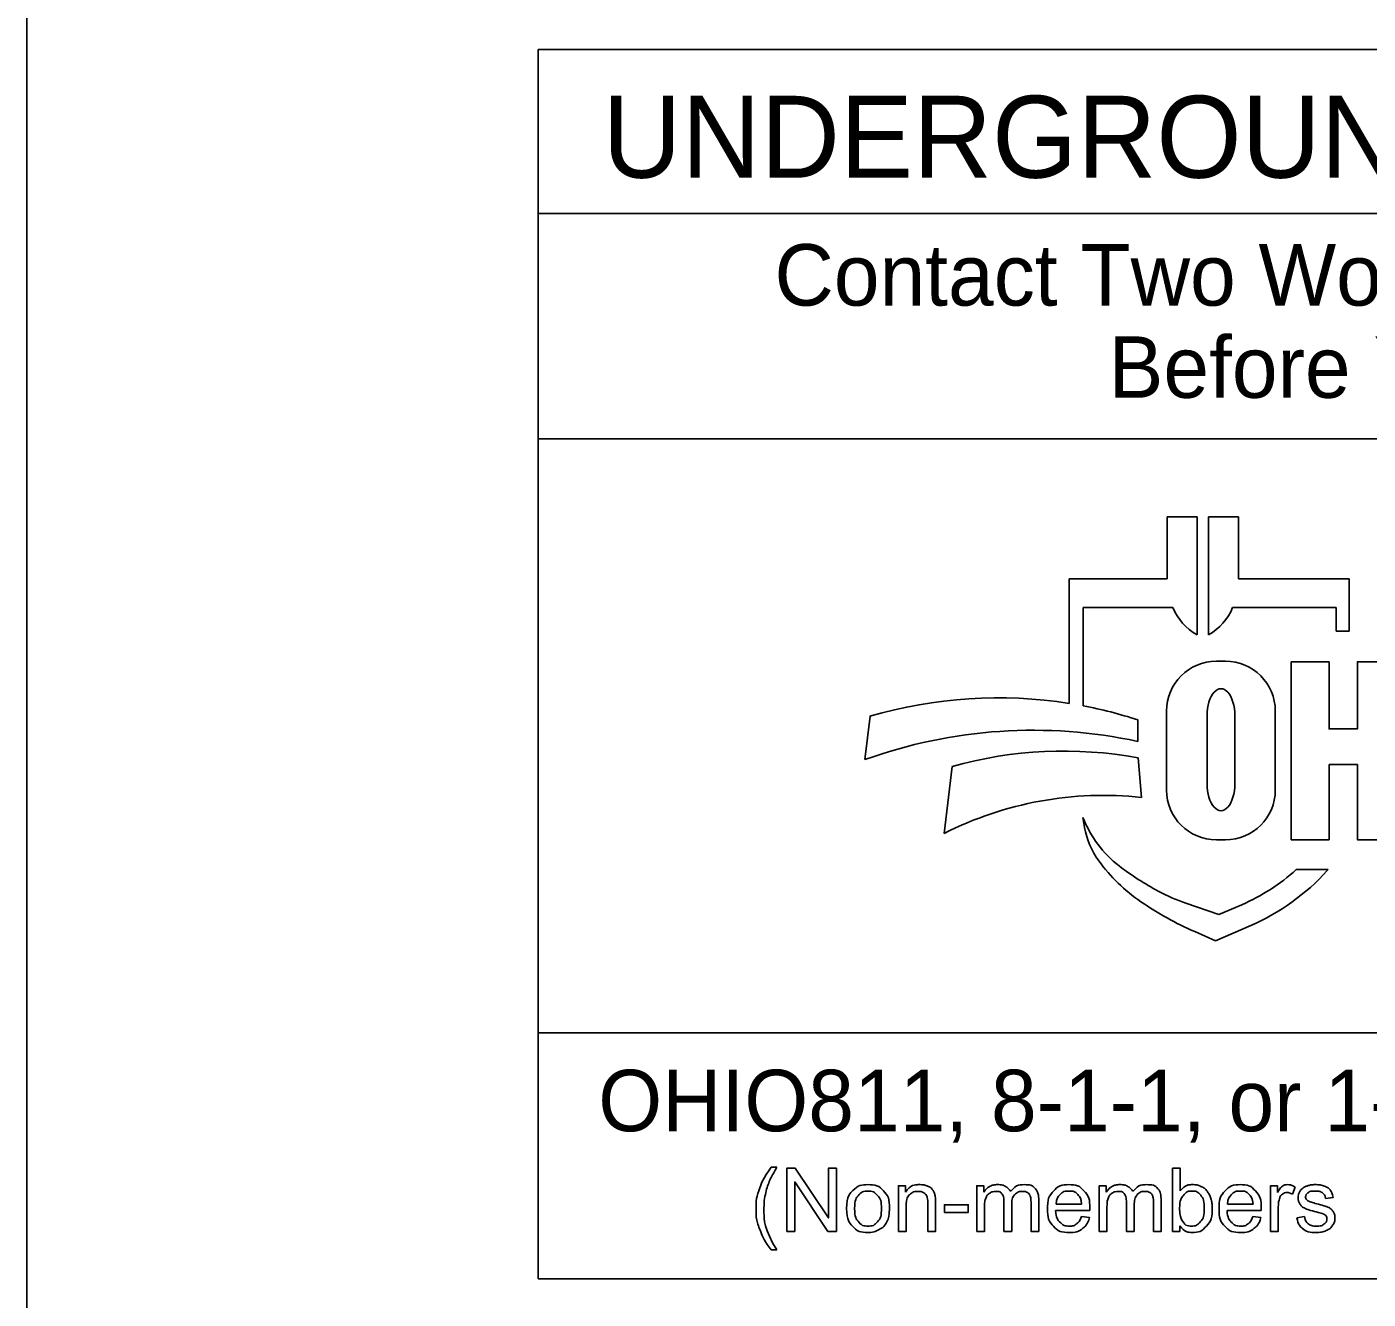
# Model space of a CAD drawing. Extents: x -19.5 to 44.1, y 0 to 22.
# Drawn here: x 2 to 5.062, y 1.775 to 4.678 of the extents above; entities that cross this region are included whole.
import ezdxf

# ---------------------------------------------------------------- set-up
doc = ezdxf.new("R2010")
doc.units = 0
doc.layers.add('SH_Border', color=7, linetype='Continuous')
doc.layers.add('SH_Data', color=7, linetype='Continuous')

msp = doc.modelspace()

# ---------------------------------------------------------------- linework, layer by layer
at = {"layer": 'SH_Border'}
msp.add_lwpolyline([(2, 21.5), (33.5, 21.5), (33.5, 0.5), (2, 0.5)], close=True, dxfattribs=at)
at = {"layer": 'SH_Data'}
for p, q in [((3.1673, 4.6264), (7.6086, 4.6264)), ((3.1673, 1.8214), (3.1673, 4.6264)), ((3.1673, 4.2524), (7.6086, 4.2524)), ((3.1673, 3.7382), (7.6086, 3.7382)), ((4.671, 3.5601), (4.6029, 3.5601)), ((4.6029, 3.5601), (4.6029, 3.4185)), ((4.671, 3.2908), (4.671, 3.5601)), ((4.7655, 3.5601), (4.6974, 3.5601)), ((4.6974, 3.5601), (4.6974, 3.2908)), ((4.7655, 3.4185), (4.7655, 3.5601)), ((4.6029, 3.4185), (4.3794, 3.4185)), ((4.3794, 3.4185), (4.3794, 3.1343)), ((5.0185, 3.4185), (4.7655, 3.4185)), ((5.0185, 3.2994), (5.0185, 3.4185)), ((4.4115, 3.1287), (4.4115, 3.3532)), ((4.4115, 3.3532), (4.6161, 3.3532)), ((4.7523, 3.3532), (4.9889, 3.3532)), ((4.9889, 3.3532), (4.9889, 3.2994)), ((4.9889, 3.2994), (5.0185, 3.2994)), ((4.7361, 3.2305), (4.7152, 3.2305)), ((4.9724, 3.2293), (4.8861, 3.2293)), ((4.8861, 3.2293), (4.8861, 2.823)), ((3.9246, 3.1052), (3.9127, 3.006)), ((4.5357, 3.0476), (4.5357, 3.0969)), ((4.6015, 3.1169), (4.6015, 2.9366)), ((4.6941, 2.951), (4.6941, 3.1064)), ((4.7573, 3.1064), (4.7573, 2.951)), ((4.8497, 2.9366), (4.8497, 3.1169)), ((4.5443, 2.9197), (4.5364, 3.0098)), ((4.1121, 2.9902), (4.0935, 2.8377)), ((4.9724, 2.823), (4.9724, 2.9947)), ((4.4106, 2.8741), (4.4145, 2.8513)), ((4.7152, 2.823), (4.7361, 2.823)), ((4.8861, 2.823), (4.9724, 2.823)), ((4.9703, 2.755), (4.8974, 2.755)), ((4.9683, 2.7527), (4.9703, 2.755)), ((4.7209, 2.6523), (4.6454, 2.6783)), ((4.773, 2.6749), (4.7209, 2.6523)), ((4.6658, 2.6135), (4.7132, 2.5926)), ((4.7132, 2.5926), (4.7936, 2.6275)), ((7.6086, 2.3825), (3.1673, 2.3825)), ((7.6086, 1.8214), (3.1673, 1.8214))]:
    msp.add_line(p, q, dxfattribs=at)
for points in [[(4.9724, 2.9947), (5.0371, 2.9947), (5.0371, 2.823), (5.1234, 2.823), (5.1234, 3.2293), (5.0371, 3.2293), (5.0371, 3.076), (4.9724, 3.076), (4.9724, 3.2293)], [(3.6993, 2.0757), (3.7119, 2.0757)], [(3.7345, 1.9293), (3.7345, 2.0733), (3.754, 2.0733), (3.8298, 1.9602), (3.8298, 2.0733), (3.848, 2.0733), (3.848, 1.9293), (3.8285, 1.9293), (3.7527, 2.0424), (3.7527, 1.9293), (3.7345, 1.9293)], [(4.6316, 1.9293), (4.6153, 1.9293), (4.6153, 2.0733), (4.6329, 2.0733), (4.6329, 2.022)], [(3.9896, 1.9293), (3.9896, 2.0337), (4.0055, 2.0337), (4.0055, 2.0188)], [(4.1683, 1.9293), (4.1683, 2.0337), (4.1841, 2.0337), (4.1841, 2.0189)], [(4.4478, 1.9293), (4.4478, 2.0337), (4.4636, 2.0337), (4.4636, 2.0189)], [(4.8388, 1.9293), (4.8388, 2.0337), (4.8547, 2.0337), (4.8547, 2.0179)], [(4.8954, 2.0303), (4.8893, 2.014)], [(4.0743, 1.9934), (4.0743, 1.9293), (4.0566, 1.9293), (4.0566, 1.9927)], [(4.0944, 1.9725), (4.0944, 1.9903), (4.1488, 1.9903), (4.1488, 1.9725), (4.0944, 1.9725)], [(4.248, 1.9899), (4.248, 1.9293), (4.2303, 1.9293), (4.2303, 1.997)], [(4.3098, 2.0009), (4.3098, 1.9293), (4.2921, 1.9293), (4.2921, 1.995)], [(4.3492, 1.9914), (4.4075, 1.9914)], [(4.5274, 1.9899), (4.5274, 1.9293), (4.5098, 1.9293), (4.5098, 1.997)], [(4.5892, 2.0009), (4.5892, 1.9293), (4.5716, 1.9293), (4.5716, 1.995)], [(4.7405, 1.9914), (4.7988, 1.9914)], [(4.9817, 2.0067), (4.9644, 2.0044)], [(4.0072, 1.9862), (4.0072, 1.9293), (3.9896, 1.9293)], [(4.186, 1.9834), (4.186, 1.9293), (4.1683, 1.9293)], [(4.4261, 1.9769), (4.3482, 1.9769)], [(4.4073, 1.963), (4.4256, 1.9607)], [(4.4654, 1.9834), (4.4654, 1.9293), (4.4478, 1.9293)], [(4.8173, 1.9769), (4.7395, 1.9769)], [(4.7986, 1.963), (4.8168, 1.9607)], [(4.8565, 1.9839), (4.8565, 1.9293), (4.8388, 1.9293)], [(4.8988, 1.9605), (4.9163, 1.9632)], [(4.6316, 1.9424), (4.6316, 1.9293)], [(3.7119, 1.8869), (3.6993, 1.8869)]]:
    msp.add_lwpolyline(points, dxfattribs=at)
for centre, radius, start, end in [((4.7321, 3.3999), 0.125, 201.9296, 240.7469), ((4.6363, 3.3999), 0.125, 299.2531, 338.0704), ((4.7152, 3.1169), 0.1136, 90, 180), ((4.7361, 3.1169), 0.1136, 0, 90), ((4.2167, 2.1071), 1.04, 81.0007, 106.3144), ((4.2167, 2.1071), 1.04, 72.1402, 79.2074), ((4.2968, 1.9406), 1.1325, 77.8238, 109.8274), ((4.366, 2.0959), 0.9297, 79.44, 105.8467), ((4.4575, 2.1172), 0.8072, 83.8248, 116.8021), ((4.7152, 2.9366), 0.1136, 180, 270), ((4.7361, 2.9366), 0.1136, 270, 0), ((4.6486, 2.9656), 0.2549, 201.0457, 232.5314), ((4.5939, 2.8819), 0.182, 189.6817, 216.0884), ((4.7637, 3.0057), 0.392, 216.0884, 235.7167), ((4.8931, 3.2846), 0.6568, 232.5314, 241.794), ((4.5909, 3.0945), 0.4574, 293.4582, 312.0712), ((4.5909, 3.0945), 0.5091, 293.4582, 317.8286), ((4.7849, 3.083), 0.428, 241.794, 250.9821), ((4.9751, 3.3158), 0.7674, 235.7167, 246.2325)]:
    msp.add_arc(centre, radius, start, end, dxfattribs=at)
for centre, start_param, end_param in [((4.7257, 3.1064), 4.712389, 7.853982), ((4.7257, 2.951), 1.570796, 4.712389)]:
    msp.add_ellipse(centre, major_axis=(0, 0.0615), ratio=0.514403, start_param=start_param, end_param=end_param, dxfattribs=at)
for points in [[(3.6993, 1.8869), (3.6846, 1.9054), (3.6745, 1.9302), (3.6644, 1.9549), (3.6644, 1.9814), (3.6644, 2.0048), (3.672, 2.0262), (3.6808, 2.0511), (3.6993, 2.0757)], [(3.7119, 2.0757), (3.7001, 2.0553), (3.6962, 2.0465), (3.6903, 2.033), (3.6868, 2.0182), (3.6826, 1.9999), (3.6826, 1.9813), (3.6826, 1.9341), (3.7119, 1.8869)], [(3.8712, 1.9815), (3.8712, 2.0104), (3.8873, 2.0244), (3.9007, 2.036), (3.92, 2.036), (3.9415, 2.036), (3.9552, 2.0219), (3.9688, 2.0078), (3.9688, 1.983), (3.9688, 1.9628), (3.9628, 1.9513), (3.9568, 1.9398), (3.9452, 1.9334), (3.9337, 1.927), (3.92, 1.927), (3.8982, 1.927), (3.8847, 1.941), (3.8712, 1.9551), (3.8712, 1.9815)], [(3.8894, 1.9815), (3.8894, 1.9614), (3.8981, 1.9515), (3.9068, 1.9415), (3.92, 1.9415), (3.9332, 1.9415), (3.9419, 1.9515), (3.9506, 1.9615), (3.9506, 1.9821), (3.9506, 2.0014), (3.9418, 2.0114), (3.9331, 2.0214), (3.92, 2.0214), (3.9068, 2.0214), (3.8981, 2.0115), (3.8894, 2.0015), (3.8894, 1.9815)], [(4.0055, 2.0188), (4.017, 2.036), (4.0387, 2.036), (4.0481, 2.036), (4.056, 2.0326), (4.0639, 2.0292), (4.0678, 2.0237), (4.0718, 2.0182), (4.0733, 2.0106), (4.0743, 2.0057), (4.0743, 1.9934)], [(4.1841, 2.0189), (4.1891, 2.0266), (4.1972, 2.0313), (4.2054, 2.036), (4.2158, 2.036), (4.2274, 2.036), (4.2348, 2.0312), (4.2422, 2.0263), (4.2453, 2.0177), (4.2577, 2.036), (4.2775, 2.036), (4.2931, 2.036), (4.3014, 2.0274), (4.3098, 2.0188), (4.3098, 2.0009)], [(4.4256, 1.9607), (4.4212, 1.9447), (4.4096, 1.9358), (4.3979, 1.927), (4.3797, 1.927), (4.3568, 1.927), (4.3434, 1.9411), (4.33, 1.9552), (4.33, 1.9806), (4.33, 2.0069), (4.3436, 2.0214), (4.3571, 2.036), (4.3787, 2.036), (4.3996, 2.036), (4.4129, 2.0217), (4.4262, 2.0075), (4.4262, 1.9816), (4.4262, 1.9801), (4.4261, 1.9769)], [(4.4075, 1.9914), (4.4063, 2.0046), (4.4008, 2.0112), (4.3924, 2.0215), (4.3789, 2.0215), (4.3667, 2.0215), (4.3584, 2.0133), (4.3501, 2.0051), (4.3492, 1.9914)], [(4.4636, 2.0189), (4.4685, 2.0266), (4.4766, 2.0313), (4.4848, 2.036), (4.4952, 2.036), (4.5068, 2.036), (4.5142, 2.0312), (4.5216, 2.0263), (4.5247, 2.0177), (4.5371, 2.036), (4.557, 2.036), (4.5725, 2.036), (4.5809, 2.0274), (4.5892, 2.0188), (4.5892, 2.0009)], [(4.6314, 1.9823), (4.6314, 1.9635), (4.6365, 1.9551), (4.6448, 1.9415), (4.659, 1.9415), (4.6706, 1.9415), (4.679, 1.9516), (4.6875, 1.9616), (4.6875, 1.9816), (4.6875, 2.002), (4.6794, 2.0118), (4.6713, 2.0215), (4.6598, 2.0215), (4.6483, 2.0215), (4.6398, 2.0114), (4.6314, 2.0013), (4.6314, 1.9823)], [(4.6329, 2.022), (4.6441, 2.036), (4.6615, 2.036), (4.6711, 2.036), (4.6797, 2.0321), (4.6883, 2.0282), (4.6939, 2.0212), (4.6994, 2.0142), (4.7025, 2.0043), (4.7057, 1.9943), (4.7057, 1.9831), (4.7057, 1.9563), (4.6924, 1.9416), (4.6792, 1.927), (4.6606, 1.927), (4.6421, 1.927), (4.6316, 1.9424)], [(4.8168, 1.9607), (4.8125, 1.9447), (4.8008, 1.9358), (4.7891, 1.927), (4.771, 1.927), (4.7481, 1.927), (4.7347, 1.9411), (4.7213, 1.9552), (4.7213, 1.9806), (4.7213, 2.0069), (4.7348, 2.0214), (4.7484, 2.036), (4.77, 2.036), (4.7909, 2.036), (4.8042, 2.0217), (4.8174, 2.0075), (4.8174, 1.9816), (4.8174, 1.9801), (4.8173, 1.9769)], [(4.7988, 1.9914), (4.7976, 2.0046), (4.7921, 2.0112), (4.7836, 2.0215), (4.7702, 2.0215), (4.758, 2.0215), (4.7497, 2.0133), (4.7414, 2.0051), (4.7405, 1.9914)], [(4.8547, 2.0179), (4.8608, 2.0289), (4.866, 2.0324), (4.8711, 2.036), (4.8773, 2.036), (4.8862, 2.036), (4.8954, 2.0303)], [(4.9644, 2.0044), (4.9632, 2.0124), (4.9575, 2.017), (4.9519, 2.0215), (4.9415, 2.0215), (4.9294, 2.0215), (4.9241, 2.0175), (4.9189, 2.0134), (4.9189, 2.008), (4.9189, 2.0046), (4.9211, 2.0018), (4.9233, 1.999), (4.9279, 1.9971), (4.9305, 1.9961), (4.9435, 1.9926), (4.9623, 1.9876), (4.9697, 1.9844), (4.9772, 1.9812), (4.9814, 1.9751), (4.9857, 1.969), (4.9857, 1.96), (4.9857, 1.9511), (4.9805, 1.9433), (4.9753, 1.9355), (4.9656, 1.9313), (4.9558, 1.927), (4.9435, 1.927), (4.9232, 1.927), (4.9125, 1.9354), (4.9018, 1.9439), (4.8988, 1.9605)], [(4.9163, 1.9632), (4.9178, 1.9527), (4.9245, 1.9471), (4.9313, 1.9415), (4.9434, 1.9415), (4.9556, 1.9415), (4.9615, 1.9464), (4.9674, 1.9514), (4.9674, 1.9581), (4.9674, 1.9641), (4.9622, 1.9676), (4.9586, 1.9699), (4.9441, 1.9736), (4.9246, 1.9785), (4.9171, 1.982), (4.9096, 1.9856), (4.9057, 1.992), (4.9018, 1.9983), (4.9018, 2.0059), (4.9018, 2.0129), (4.905, 2.0188), (4.9082, 2.0248), (4.9137, 2.0287), (4.9178, 2.0318), (4.925, 2.0339), (4.9321, 2.036), (4.9403, 2.036), (4.9526, 2.036), (4.9619, 2.0324), (4.9712, 2.0289), (4.9756, 2.0228), (4.98, 2.0168), (4.9817, 2.0067)], [(4.0566, 1.9927), (4.0566, 2.0035), (4.0546, 2.0089), (4.0525, 2.0142), (4.0473, 2.0174), (4.042, 2.0206), (4.0349, 2.0206), (4.0236, 2.0206), (4.0154, 2.0134), (4.0072, 2.0063), (4.0072, 1.9862)], [(4.2303, 1.997), (4.2303, 2.0088), (4.226, 2.0147), (4.2217, 2.0206), (4.2119, 2.0206), (4.2044, 2.0206), (4.1981, 2.0167), (4.1917, 2.0128), (4.1889, 2.0052), (4.186, 1.9976), (4.186, 1.9834)], [(4.2921, 1.995), (4.2921, 2.0056), (4.2904, 2.0103), (4.2887, 2.0149), (4.2842, 2.0178), (4.2797, 2.0206), (4.2736, 2.0206), (4.2626, 2.0206), (4.2553, 2.0133), (4.248, 2.006), (4.248, 1.9899)], [(4.5098, 1.997), (4.5098, 2.0088), (4.5054, 2.0147), (4.5011, 2.0206), (4.4913, 2.0206), (4.4838, 2.0206), (4.4775, 2.0167), (4.4711, 2.0128), (4.4683, 2.0052), (4.4654, 1.9976), (4.4654, 1.9834)], [(4.5716, 1.995), (4.5716, 2.0056), (4.5698, 2.0103), (4.5681, 2.0149), (4.5636, 2.0178), (4.5591, 2.0206), (4.553, 2.0206), (4.542, 2.0206), (4.5347, 2.0133), (4.5274, 2.006), (4.5274, 1.9899)], [(4.8893, 2.014), (4.8828, 2.0178), (4.8763, 2.0178), (4.8706, 2.0178), (4.866, 2.0143), (4.8614, 2.0108), (4.8594, 2.0046), (4.8565, 1.9952), (4.8565, 1.9839)], [(4.3482, 1.9769), (4.3492, 1.9597), (4.358, 1.9506), (4.3667, 1.9415), (4.3798, 1.9415), (4.3895, 1.9415), (4.3964, 1.9466), (4.4033, 1.9517), (4.4073, 1.963)], [(4.7395, 1.9769), (4.7405, 1.9597), (4.7492, 1.9506), (4.758, 1.9415), (4.771, 1.9415), (4.7808, 1.9415), (4.7876, 1.9466), (4.7945, 1.9517), (4.7986, 1.963)]]:
    msp.add_open_spline(points, degree=3, dxfattribs=at)

# ---------------------------------------------------------------- texts
for s, height, p in [('UNDERGROUND UTILITIES', 0.187, (3.314, 4.3341)), ('Contact Two Working Days', 0.14025, (3.7066, 4.0422)), ('Before You Dig', 0.14025, (4.4691, 3.8318)), ('OHIO811, 8-1-1, or 1-800-362-2764', 0.14025, (3.3043, 2.1579))]:
    msp.add_text(s, height=height, dxfattribs=at).set_placement(p)

doc.saveas('drawing.dxf')
